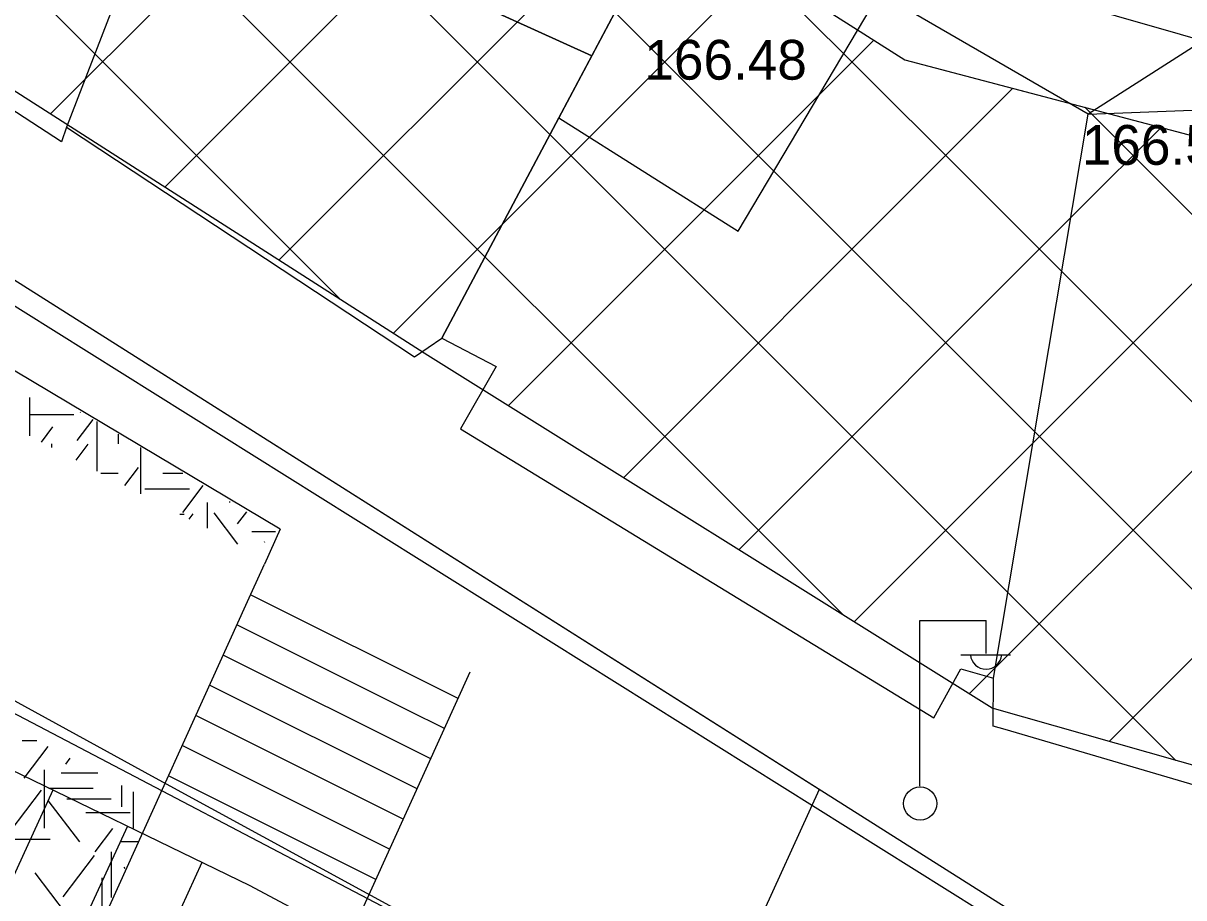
# Model space of a CAD drawing. Extents: x 419677 to 421689, y 4450851 to 4452923.
# Drawn here: x 420321.68 to 420356.74, y 4452004.01 to 4452030.41 of the extents above; entities that cross this region are included whole.
import ezdxf

# ---------------------------------------------------------------- set-up
doc = ezdxf.new("R2010")
doc.units = 0
for name, color, linetype in [('AA_HH', 7, 'Continuous'), ('Level 10', 7, 'Continuous'), ('Level 27', 7, 'Continuous'), ('Level 28', 7, 'Continuous'), ('Level 34', 7, 'Continuous'), ('Level 41', 7, 'Continuous'), ('Level 62', 7, 'Continuous'), ('Level 9', 7, 'Continuous')]:
    doc.layers.add(name, color=color, linetype=linetype)

msp = doc.modelspace()

# ---------------------------------------------------------------- linework, layer by layer
at = {"layer": 'AA_HH'}
for p, q in [((420348.764, 4452007.378), (420348.764, 4452012.378)), ((420348.764, 4452012.378), (420350.764, 4452012.378)), ((420350.764, 4452011.378), (420350.764, 4452012.378)), ((420350.004, 4452011.338), (420351.504, 4452011.338)), ((420322.581, 4452007.258), (420319.316, 4452000.156)), ((420324.831, 4452006.167), (420323.209, 4452002.639)), ((420327.081, 4452005.075), (420323.859, 4451998.067))]:
    msp.add_line(p, q, dxfattribs=at)
for points in [[(420420.283, 4451972.04), (420421.029, 4451970.095), (420421.342, 4451968.715), (420420.96, 4451967.485), (420420.456, 4451967.019), (420419.682, 4451966.656), (420419.467, 4451966.604), (420419.102, 4451966.589), (420380.556, 4451986.723), (420357.561, 4451999.25), (420318.688, 4452023.585), (420304.823, 4452033.943), (420285.337, 4452050.002), (420272.264, 4452064.398), (420263.435, 4452076.857), (420254.665, 4452090.863), (420245.178, 4452107.602), (420239.444, 4452119.113), (420237.151, 4452126.743), (420229.958, 4452160.587), (420223.737, 4452191.2), (420219.459, 4452205.797)], [(420397.569, 4451969.565), (420368.162, 4451984.791), (420346.871, 4451996.077), (420325.677, 4452007.623), (420307.1, 4452017.8), (420297.551, 4452023.383), (420287.987, 4452030.11), (420276.408, 4452038.563), (420264.859, 4452049.332), (420260.081, 4452053.957), (420259.882, 4452054.112), (420260.728, 4452041.699), (420259.985, 4452032.196), (420258.843, 4452024.529), (420255.051, 4452011.924), (420250.679, 4452002.57), (420243.311, 4451990.758), (420238.509, 4451984.736), (420246.006, 4451983.783), (420257.774, 4451981.835), (420271.403, 4451978.695), (420279.405, 4451976.372)], [(420438.02, 4451947.439), (420433.413, 4451950.307), (420401.754, 4451966.128), (420364.854, 4451984.999), (420328.536, 4452004.369), (420296.842, 4452019.746), (420270.508, 4452033.174), (420265.237, 4452035.449), (420263.701, 4452035.377)], [(420402.354, 4452030.324), (420379.328, 4452029.072), (420371.637, 4452029.936), (420358.086, 4452030.374), (420353.849, 4452027.662)]]:
    msp.add_lwpolyline(points, dxfattribs=at)
for points in [[(420328.054, 4452042.52), (420327.504, 4452040.743), (420325.427, 4452033.582), (420331.288, 4452032.871), (420338.855, 4452029.424), (420339.966, 4452031.525), (420340.852, 4452035.042), (420341.876, 4452038.48)], [(420311.79, 4452040.565), (420326.401, 4452036.941), (420325.427, 4452033.582), (420322.994, 4452027.277), (420322.84, 4452026.834), (420310.169, 4452035.09)], [(420334.887, 4452018.168), (420349.19, 4452009.439), (420349.999, 4452010.924), (420350.986, 4452010.638), (420353.849, 4452027.662), (420347.543, 4452031.315), (420340.852, 4452035.042), (420339.966, 4452031.525), (420337.865, 4452027.552), (420334.327, 4452020.898), (420335.973, 4452020.049)], [(420340.852, 4452035.042), (420339.966, 4452031.525), (420337.865, 4452027.552), (420343.282, 4452024.138), (420347.543, 4452031.315)], [(420325.427, 4452033.582), (420322.994, 4452027.277), (420333.507, 4452020.339), (420334.327, 4452020.898), (420337.865, 4452027.552), (420338.855, 4452029.424), (420331.288, 4452032.871)], [(420353.849, 4452027.662), (420361.429, 4452027.961), (420429.01, 4452008.391), (420427.99, 4451986.978), (420390.303, 4451997.935), (420388.649, 4452001.016), (420382.267, 4452002.948), (420378.953, 4452000.968), (420351.338, 4452009.089), (420350.976, 4452009.185), (420350.986, 4452010.638)]]:
    msp.add_lwpolyline(points, close=True, dxfattribs=at)
msp.add_circle((420348.774, 4452006.853), 0.5, dxfattribs=at)
msp.add_arc((420350.764, 4452011.381), 0.474, 184.8384, 355.1464, dxfattribs=at)
at = {"layer": 'Level 10'}
msp.add_line((420345.721, 4452007.281), (420295.814, 4452038.838), dxfattribs=at)
for points in [[(420310.312, 4452088.984), (420309.767, 4452087.535), (420336.779, 4452078.43), (420328.838, 4452046.411), (420341.019, 4452034.555), (420411.384, 4452014.406)], [(420345.721, 4452007.281), (420343.737, 4452002.924)]]:
    msp.add_lwpolyline(points, dxfattribs=at)
at = {"layer": 'Level 27'}
msp.add_lwpolyline([(420425.863, 4451988.129), (420392.21, 4451997.82), (420377.38, 4452002.22), (420350.95, 4452009.73), (420333.9, 4452020.38), (420310.3, 4452035.49), (420300.451, 4452044.999)], dxfattribs=at)
msp.add_lwpolyline([(420425.863, 4451988.129), (420392.21, 4451997.82), (420377.38, 4452002.22), (420350.95, 4452009.73), (420333.9, 4452020.38), (420310.3, 4452035.49), (420300.451, 4452044.999)], dxfattribs=at)
at = {"layer": 'Level 28'}
for points in [[(420333.035, 4452072.273), (420324.731, 4452044.259), (420348.308, 4452029.309)], [(420333.035, 4452072.273), (420324.731, 4452044.259), (420348.308, 4452029.309)], [(420348.308, 4452029.309), (420428.79, 4452008.08)], [(420348.308, 4452029.309), (420428.79, 4452008.08)]]:
    msp.add_lwpolyline(points, dxfattribs=at)
at = {"layer": 'Level 34'}
for p, q in [((420356.495, 4452008.155), (420304.761, 4452059.888)), ((420356.495, 4452008.155), (420304.761, 4452059.888)), ((420346.454, 4452012.538), (420303.41, 4452055.582)), ((420346.454, 4452012.538), (420303.41, 4452055.582)), ((420331.274, 4452022.061), (420302.141, 4452051.195)), ((420331.274, 4452022.061), (420302.141, 4452051.195)), ((420322.512, 4452027.672), (420331.388, 4452036.548)), ((420322.512, 4452027.672), (420331.388, 4452036.548)), ((420325.96, 4452025.463), (420334.736, 4452034.239)), ((420325.96, 4452025.463), (420334.736, 4452034.239)), ((420329.409, 4452023.255), (420338.084, 4452031.93)), ((420329.409, 4452023.255), (420338.084, 4452031.93)), ((420341.432, 4452029.621), (420343.909, 4452032.098)), ((420341.432, 4452029.621), (420343.909, 4452032.098)), ((420349.717, 4452026.246), (420343.787, 4452032.176)), ((420349.717, 4452026.246), (420343.787, 4452032.176)), ((420364.397, 4452005.909), (420339.024, 4452031.282)), ((420364.397, 4452005.909), (420339.024, 4452031.282)), ((420345.388, 4452027.921), (420347.371, 4452029.904)), ((420345.388, 4452027.921), (420347.371, 4452029.904)), ((420332.858, 4452021.047), (420341.432, 4452029.621)), ((420332.858, 4452021.047), (420341.432, 4452029.621)), ((420349.467, 4452026.343), (420351.572, 4452028.448)), ((420349.467, 4452026.343), (420351.572, 4452028.448)), ((420336.33, 4452018.862), (420345.388, 4452027.921)), ((420336.33, 4452018.862), (420345.388, 4452027.921)), ((420345.388, 4452027.921), (420345.388, 4452027.921)), ((420345.388, 4452027.921), (420345.388, 4452027.921)), ((420358.943, 4452022.677), (420353.745, 4452027.875)), ((420358.943, 4452022.677), (420353.745, 4452027.875)), ((420353.546, 4452024.765), (420356.048, 4452027.268)), ((420353.546, 4452024.765), (420356.048, 4452027.268)), ((420339.812, 4452016.687), (420349.467, 4452026.343)), ((420339.812, 4452016.687), (420349.467, 4452026.343)), ((420363.547, 4452012.416), (420349.717, 4452026.246)), ((420363.547, 4452012.416), (420349.717, 4452026.246)), ((420343.294, 4452014.512), (420353.546, 4452024.765)), ((420343.294, 4452014.512), (420353.546, 4452024.765)), ((420346.776, 4452012.338), (420357.625, 4452023.187)), ((420346.776, 4452012.338), (420357.625, 4452023.187)), ((420350.257, 4452010.163), (420361.849, 4452021.754)), ((420350.257, 4452010.163), (420361.849, 4452021.754)), ((420354.479, 4452008.727), (420363.116, 4452017.364)), ((420354.479, 4452008.727), (420363.116, 4452017.364))]:
    msp.add_line(p, q, dxfattribs=at)
at = {"layer": 'Level 41'}
for p, q in [((420321.87, 4452019.11), (420321.87, 4452017.95)), ((420323.419, 4452018.658), (420323.408, 4452018.673)), ((420321.87, 4452018.596), (420323.213, 4452018.596)), ((420323.312, 4452017.816), (420323.795, 4452018.452)), ((420323.912, 4452018.386), (420323.912, 4452016.887)), ((420322.232, 4452017.762), (420322.584, 4452018.225)), ((420324.556, 4452018.005), (420324.556, 4452017.712)), ((420322.542, 4452017.712), (420322.542, 4452017.6)), ((420323.282, 4452017.215), (420323.65, 4452017.7)), ((420325.228, 4452017.599), (420325.228, 4452016.203)), ((420324.752, 4452016.45), (420325.169, 4452016.998)), ((420324.025, 4452016.828), (420324.556, 4452016.828)), ((420325.899, 4452016.828), (420326.502, 4452016.828)), ((420325.359, 4452016.358), (420326.702, 4452016.358)), ((420326.509, 4452015.644), (420327.123, 4452016.452)), ((420327.242, 4452015.945), (420327.242, 4452015.162)), ((420327.914, 4452015.973), (420327.914, 4452015.945)), ((420327.914, 4452015.973), (420327.914, 4452015.945)), ((420326.418, 4452015.588), (420326.542, 4452015.588)), ((420326.701, 4452015.442), (420326.819, 4452015.597)), ((420328.171, 4452014.681), (420327.45, 4452015.63)), ((420328.16, 4452015.293), (420328.437, 4452015.657)), ((420328.585, 4452015.061), (420329.308, 4452015.061)), ((420328.982, 4452014.735), (420328.967, 4452014.755)), ((420321.654, 4452008.757), (420322.093, 4452008.757)), ((420321.715, 4452007.623), (420322.437, 4452008.574)), ((420322.967, 4452008.043), (420323.102, 4452008.22)), ((420322.326, 4452006.106), (420322.326, 4452007.874)), ((420322.831, 4452007.776), (420323.937, 4452007.776)), ((420324.658, 4452007.393), (420324.658, 4452006.751)), ((420321.29, 4452006.009), (420322.239, 4452007.259)), ((420322.457, 4452007.32), (420323.8, 4452007.32)), ((420325.012, 4452006.106), (420325.012, 4452007.204)), ((420323.393, 4452005.695), (420322.443, 4452006.944)), ((420322.997, 4452006.99), (420324.34, 4452006.99)), ((420323.576, 4452006.583), (420324.919, 4452006.583)), ((420323.859, 4452005.397), (420324.396, 4452006.103)), ((420321.153, 4452005.778), (420322.496, 4452005.778)), ((420324.615, 4452005.709), (420325.165, 4452005.709)), ((420322.887, 4452004.034), (420323.836, 4452005.284)), ((420324.34, 4452005.397), (420324.34, 4452004.015)), ((420322.994, 4452003.508), (420322.045, 4452004.757)), ((420324.058, 4452004.609), (420324.058, 4452003.436)), ((420324.766, 4452004.891), (420324.735, 4452004.932))]:
    msp.add_line(p, q, dxfattribs=at)
at = {"layer": 'Level 62'}
for p, q in [((420329.449, 4452015.134), (420313.438, 4452024.662)), ((420329.449, 4452015.134), (420313.438, 4452024.662)), ((420329.449, 4452015.134), (420313.438, 4452024.662)), ((420329.449, 4452015.134), (420328.972, 4452014.083)), ((420329.449, 4452015.134), (420328.972, 4452014.083)), ((420329.449, 4452015.134), (420328.972, 4452014.083)), ((420312.087, 4452014.455), (420412.275, 4451962.014)), ((420328.411, 4452012.846), (420328.972, 4452014.083)), ((420334.818, 4452010.028), (420328.553, 4452013.158)), ((420334.818, 4452010.028), (420328.553, 4452013.158)), ((420334.818, 4452010.028), (420328.553, 4452013.158)), ((420305.615, 4451962.606), (420328.411, 4452012.846)), ((420333.313, 4452009.664), (420328.139, 4452012.247)), ((420333.313, 4452009.664), (420328.139, 4452012.247)), ((420333.309, 4452009.666), (420328.139, 4452012.247)), ((420333.991, 4452008.206), (420327.726, 4452011.336)), ((420333.991, 4452008.206), (420327.726, 4452011.336)), ((420333.991, 4452008.206), (420327.726, 4452011.336)), ((420334.348, 4452008.992), (420335.183, 4452010.832)), ((420333.578, 4452007.295), (420327.312, 4452010.425)), ((420333.578, 4452007.295), (420327.312, 4452010.425)), ((420333.578, 4452007.295), (420327.312, 4452010.425)), ((420333.164, 4452006.383), (420326.898, 4452009.513)), ((420333.164, 4452006.383), (420326.898, 4452009.513)), ((420333.164, 4452006.383), (420326.898, 4452009.513)), ((420333.313, 4452009.664), (420333.309, 4452009.666)), ((420333.313, 4452009.664), (420333.309, 4452009.666)), ((420334.405, 4452009.118), (420333.314, 4452009.663)), ((420334.405, 4452009.118), (420333.314, 4452009.663)), ((420334.405, 4452009.118), (420333.314, 4452009.663)), ((420312.135, 4451960.035), (420334.348, 4452008.992)), ((420334.348, 4452008.992), (420334.348, 4452008.992)), ((420332.751, 4452005.473), (420326.485, 4452008.602)), ((420332.751, 4452005.473), (420326.485, 4452008.602)), ((420332.751, 4452005.473), (420326.485, 4452008.602)), ((420332.337, 4452004.561), (420326.072, 4452007.691)), ((420332.337, 4452004.561), (420326.072, 4452007.691)), ((420332.337, 4452004.561), (420326.072, 4452007.691))]:
    msp.add_line(p, q, dxfattribs=at)
at = {"layer": 'Level 9'}
for q in [(420295.814, 4452038.838), (420298.525, 4452037.123), (420298.525, 4452037.123)]:
    msp.add_line((420374.111, 4451989.328), q, dxfattribs=at)
for points in [[(420334.345, 4452076.692), (420324.731, 4452044.259), (420348.309, 4452029.309)], [(420334.345, 4452076.692), (420324.731, 4452044.259), (420348.309, 4452029.309)], [(420334.345, 4452076.692), (420324.731, 4452044.259), (420348.309, 4452029.309)], [(420348.309, 4452029.309), (420429.43, 4452007.911)], [(420348.309, 4452029.309), (420428.79, 4452008.08)], [(420348.309, 4452029.309), (420428.79, 4452008.08)]]:
    msp.add_lwpolyline(points, dxfattribs=at)

# ---------------------------------------------------------------- texts
at = {"layer": 'AA_HH'}
for s, p in [('166.48', (420340.445, 4452028.708)), ('166.58', (420353.656, 4452026.137))]:
    msp.add_text(s, height=1.2, dxfattribs=at).set_placement(p)

doc.saveas('drawing.dxf')
